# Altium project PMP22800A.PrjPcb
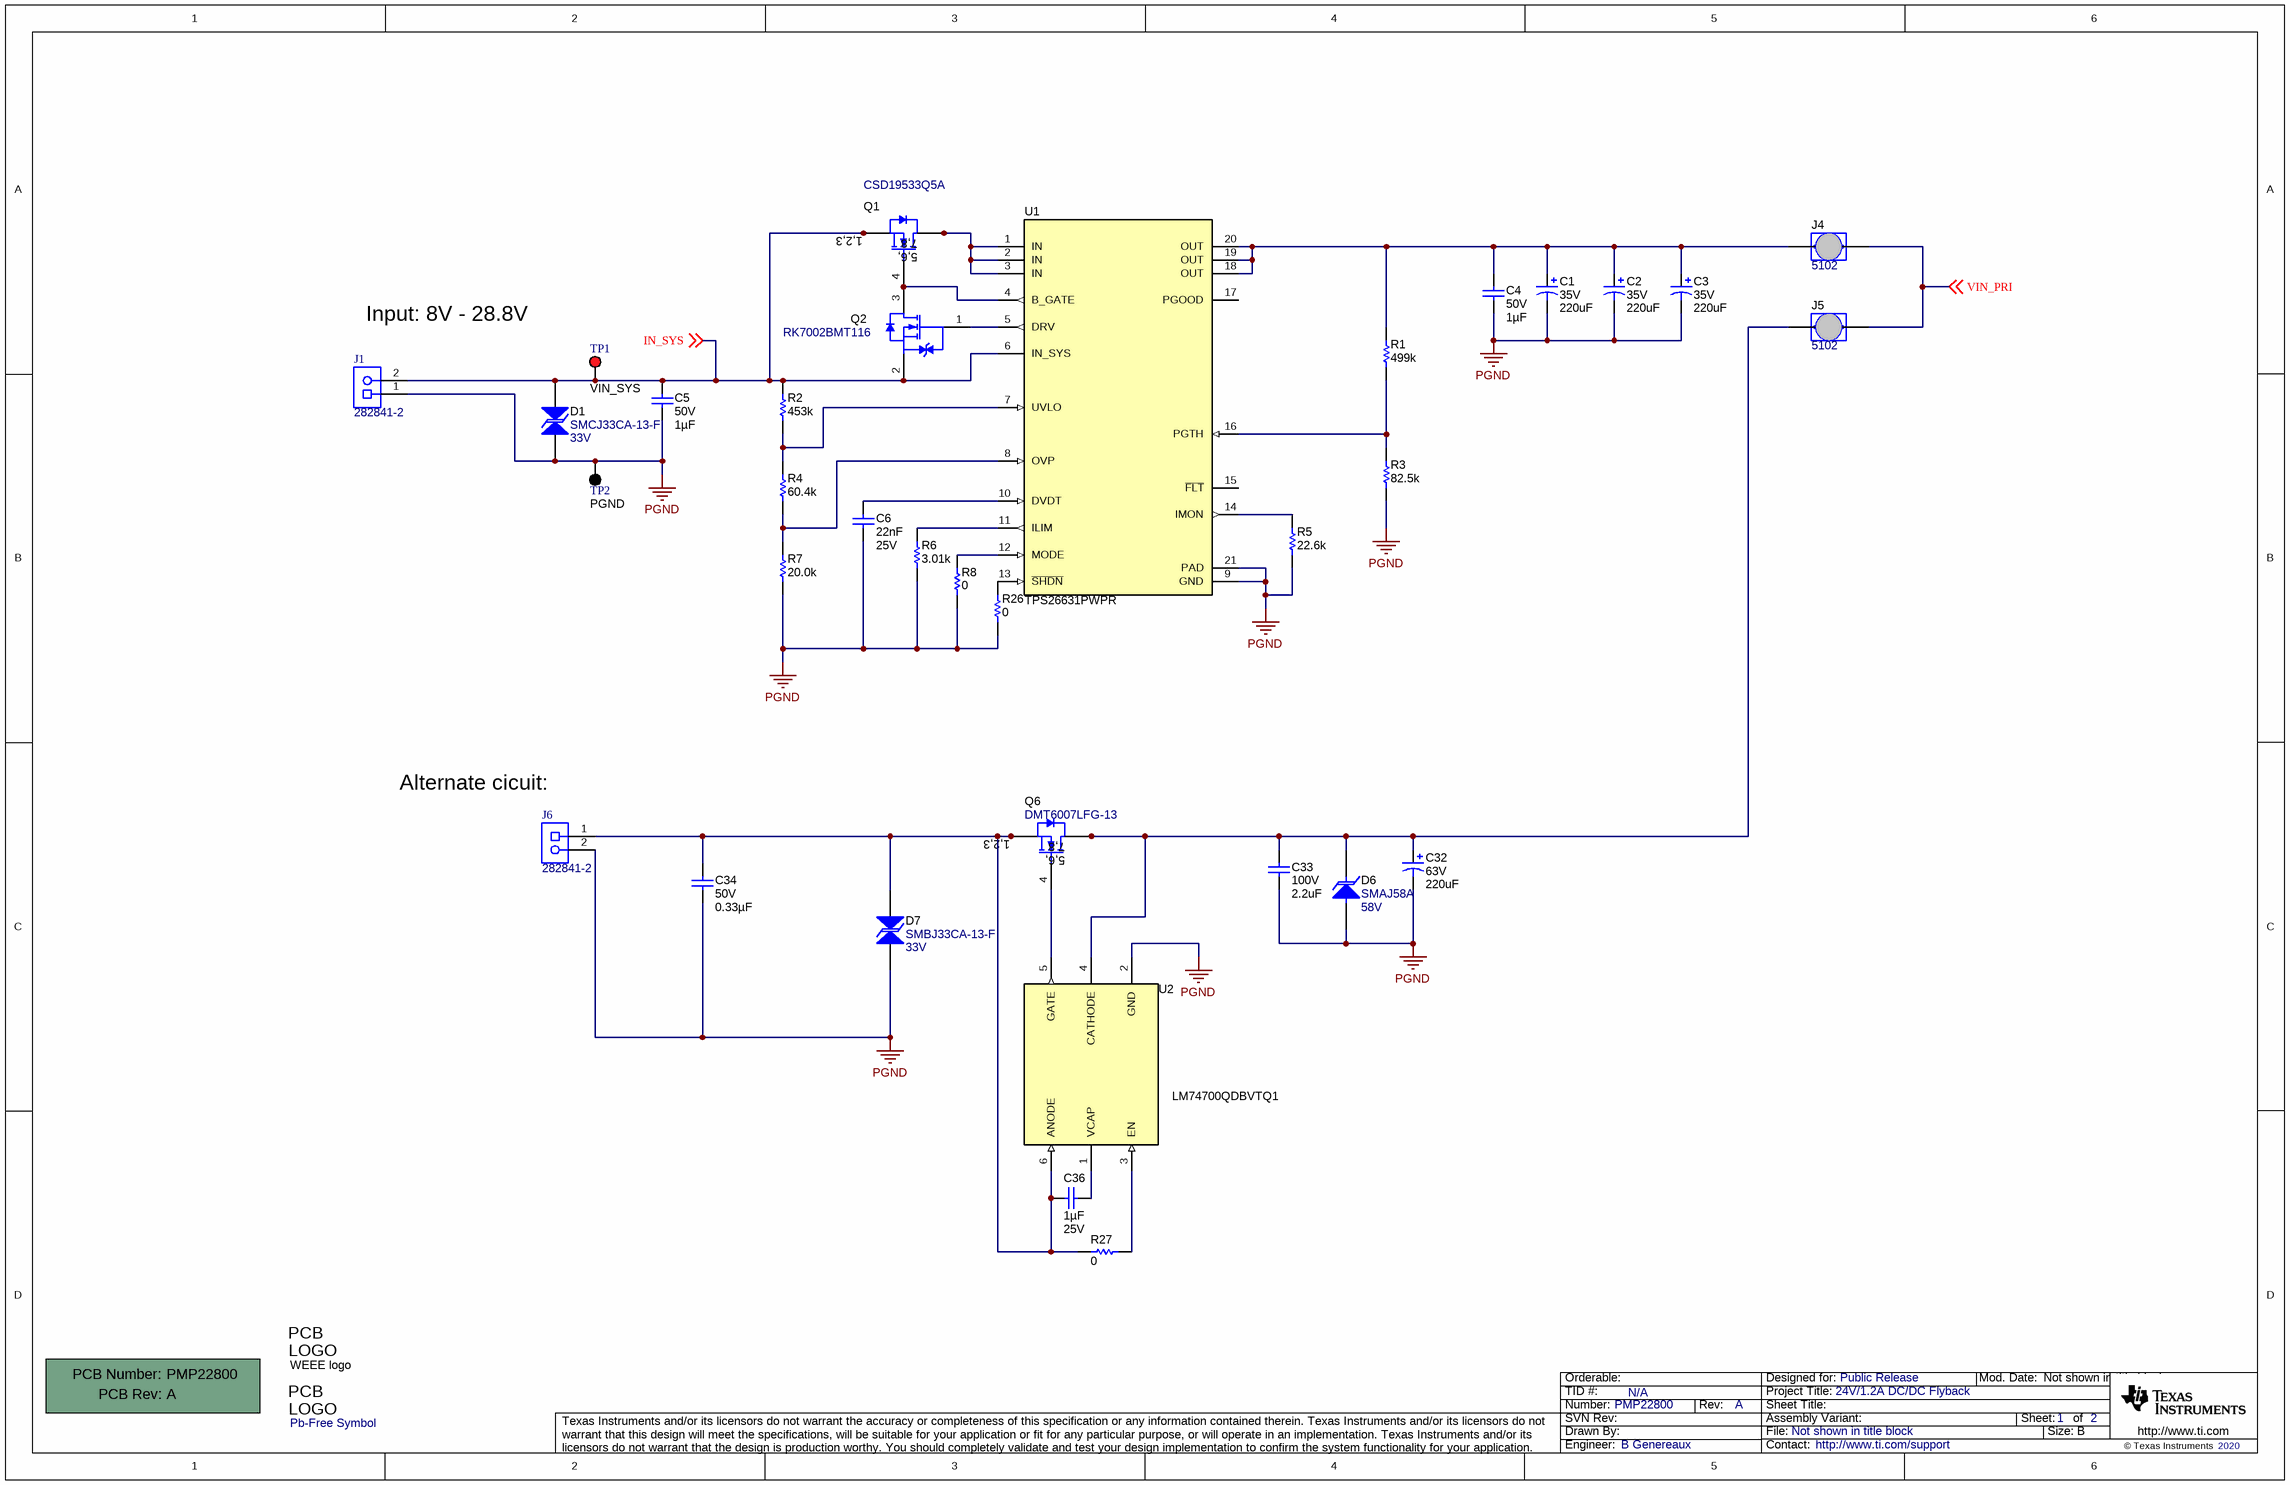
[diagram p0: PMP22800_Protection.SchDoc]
CopyrightYear: 2020; PCB_Rev: A; PRJ_Customer: Public Release; PRJ_Engineer: B Genereaux; PRJ_Number: PMP22800; PRJ_Title: 24V/1.2A DC/DC Flyback; SCH_Rev: A; TechSupport: http://www.ti.com/support; TID: N/A
2 sheets, 98 parts. Net scope: global (net labels, ports and power ports of the same name join across sheets).
Board file: PMP22800.PcbDoc
Sheets:
  PMP22800_Protection.SchDoc
  PMP22800_Power.SchDoc

## Sheet PMP22800_Protection.SchDoc
size 431 x 279 mm; Date: Not shown in title block; ApprovedBy: Not shown in title block; CheckedBy: Not shown in title block; Author: Not shown in title block; CompanyName: Not shown in title block; Engineer: Not shown in title block; Organization: Not shown in title block; Address1: Not shown in title block; Address2: Not shown in title block; Address3: Not shown in title block; Address4: Not shown in title block; DocumentNumber: 1; Revision: Use project parameter SCH_Rev; SheetNumber: 1; SheetTotal: 2; PageSetup: Record=PageOptions¦CenterHorizontal=True¦CenterVertical=True¦PrintScale=1.00¦XCorrection=1.00¦YCorrection=1.00¦PrintKind=0¦BorderSize=5000000¦LeftOffset=0¦BottomOffset=0¦Orientation=2¦PaperLength=1000¦PaperWidth=1000¦Scale=100¦PaperSource=15¦PrintQuality=600¦MediaType=1¦DitherType=10¦PaperKind=Letter¦PrintScaleMode=1

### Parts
!PCB1  Printed Circuit Board  (value not drawn)  (mechanical)
C1  VDC_V: 35V  ValueDisplayed: 220uF  [KZN_800x1500]  (hidden comment: EKZN350ELL221MH15D)
C2  VDC_V: 35V  ValueDisplayed: 220uF  [KZN_800x1500]  (hidden comment: EKZN350ELL221MH15D)
C3  VDC_V: 35V  ValueDisplayed: 220uF  [KZN_800x1500]  (hidden comment: EKZN350ELL221MH15D)
C4  VDC_V: 50V  Cap_F: 1µF  [0805_HV]  (hidden comment: GJ821BR71H105KA12L)
C5  VDC_V: 50V  Cap_F: 1µF  [0805_HV]  (hidden comment: GJ821BR71H105KA12L)
C6  Cap_F: 22nF  VDC_V: 25V  [0603]  (hidden comment: C0603C223K3RACTU)
C32  VDC_V: 63V  ValueDisplayed: 220uF  [SM_RADIAL_H13]  (hidden comment: EEV-FK1J221Q)
C33  VDC_V: 100V  ValueDisplayed: 2.2uF  [1210_210]  (hidden comment: C1210C225K1RACTU)
C34  VDC_V: 50V  ValueDisplayed: 0.33µF  [1206_180M]  (hidden comment: CGA5L2X8R1H334K160AA)
C36  Cap_F: 1µF  VDC_V: 25V  [0603]  (hidden comment: CGA3E1X7R1E105K080AD)
D1  SMCJ33CA-13-F  value 33V  [SMC_Bi]
D6  SMAJ58A  value 58V  [SMA]
D7  SMBJ33CA-13-F  value 33V  [SMB-Bi]
J1  282841-2  [TEC_282841-2]
J4  5102  [Keystone_5102]
J5  5102  [Keystone_5102]
J6  282841-2  [TEC_282841-2]
Logo1  WEEE logo  [WEEE_Minimum]  (no BOM)
Logo2  Pb-Free Symbol  [Pb-Free_Overlay_Medium]  (no BOM)
Q1  CSD19533Q5A  [DQJ0008A]
Q2  RK7002BMT116  [SOT-23_Rohm]
Q6  DMT6007LFG-13  [PowerDI3333-8]
R1  ValueDisplayed: 499k  [0603]  (hidden comment: RC0603FR-07499KL)
R2  ValueDisplayed: 453k  [0603]  (hidden comment: RC0603FR-07453KL)
R3  ValueDisplayed: 82.5k  [0603]  (hidden comment: RC0603FR-0782K5L)
R4  ValueDisplayed: 60.4k  [0603]  (hidden comment: RC0603FR-0760K4L)
R5  ValueDisplayed: 22.6k  [0603]  (hidden comment: RC0603FR-0722K6L)
R6  ValueDisplayed: 3.01k  [0603]  (hidden comment: RC0603FR-073K01L)
R7  ValueDisplayed: 20.0k  [0603]  (hidden comment: RC0603FR-0720KL)
R8  ValueDisplayed: 0  [0603]  (hidden comment: RMCF0603ZT0R00)
R26  ValueDisplayed: 0  [0603]  (hidden comment: RMCF0603ZT0R00)
R27  ValueDisplayed: 0  [0603]  (hidden comment: RMCF0603ZT0R00)
TP1  VIN_SYS  [Keystone5010]
TP2  PGND  [Keystone5011]
U1  TPS26631PWPR  [PWP0020T_N]
U2  LM74700QDBVTQ1  [DBV0006A_N]

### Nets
PGND: C1.2(-) C2.2(-) C3.2(-) C4.2 C5.2 C6.2 C32.2(-) C33.2 C34.2 D1.1 D6.2(A) D7.1 J1.1 J6.2 R3.1 R5.2 R6.2 R7.1 R8.1 R26.1 TP2.1 U1.9(GND) U1.21(PAD) U2.2(GND)
IN_SYS: C5.1 D1.2 J1.2 Q1.1(S) Q1.2(S) Q1.3(S) Q2.2(S) R2.2 TP1.1 U1.6(IN_SYS) ; off-sheet IN_SYS
VIN_PRI: J4.2 J5.2 ; off-sheet VIN_PRI
NetC1_1: C1.1(+) C2.1(+) C3.1(+) C4.1 J4.1 R1.2 U1.18(OUT) U1.19(OUT) U1.20(OUT)
NetC6_1: C6.1 U1.10(DVDT)
NetC32_1: C32.1(+) C33.1 D6.1(K) J5.1 Q6.5(D) Q6.6(D) Q6.7(D) Q6.8(D) Q6.9(D) U2.4(CATHODE)
NetC34_1: C34.1 C36.1 D7.2 J6.1 Q6.1(S) Q6.2(S) Q6.3(S) R27.2 U2.6(ANODE)
NetC36_2: C36.2 U2.1(VCAP)
NetQ1_4: Q1.4(G) Q2.3(D) U1.4(B_GATE)
NetQ1_5: Q1.5(D) Q1.6(D) Q1.7(D) Q1.8(D) Q1.9(D) U1.1(IN) U1.2(IN) U1.3(IN)
NetQ2_1: Q2.1(G) U1.5(DRV)
NetQ6_4: Q6.4(G) U2.5(GATE)
NetR1_1: R1.1 R3.2 U1.16(PGTH)
NetR2_1: R2.1 R4.2 U1.7(UVLO)
NetR4_1: R4.1 R7.2 U1.8(OVP)
NetR5_1: R5.1 U1.14(IMON)
NetR6_1: R6.1 U1.11(ILIM)
NetR8_2: R8.2 U1.12(MODE)
NetR26_2: R26.2 U1.13(~{SHDN})
NetR27_1: R27.1 U2.3(EN)

Not connected (* = marked no-connect by the designer): U1 15(~{FLT}) 17(PGOOD)

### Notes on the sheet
- Input: 8V - 28.8V
- (near J6) Alternate cicuit:

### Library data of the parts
!PCB1 = CMP-0003618-2: Manufacturer: Any; PartNumber: PMP22800
C1-C3 = CMP-0010431-2: CAP, AL, 220 uF, 35 V, +/- 20%, 0.059 ohm, TH; Manufacturer: Chemi-Con; TaMin_C: -40°C; ESR_ohm: 0.059; Polarized: Y; SizeAreaWB_mm2: 100; U/M: EA; Value: 220uF; TaMax_C: 105°C; SizeZ_mm: 16.5; SizeX_mm: 8; Cap_Case: 8x15mm; SizeArea_mm2: 64; CompType: Capacitor; Cap_F: 220µF; IRMS_A: 1.6A; AEC Category: Q200
C4 C5 = CMP-0750127-1: CAP, CERM, 1 µF, 50 V,+/- 10%, X7R, 0805; Manufacturer: MuRata; U/M: EA; SizeArea_mm2: 2.5; SizeAreaWB_mm2: 6.75; Cap_Case: 0805; Polarized: N; SizeZ_mm: 1.45; SizeX_mm: 2; TaMin_C: -55°C; Value: 1uF; TaMax_C: 125°C; SizeY_mm: 1.25; AEC Category: Q200
C6 = CMP-0006899-4: CAP, CERM, 0.022 uF, 25 V, +/- 10%, X7R, 0603; Manufacturer: Kemet; TaMin_C: -55°C; Polarized: N; SizeAreaWB_mm2: 4.68; Value1: Unknown; U/M: EA; TaMax_C: 125°C; SizeZ_mm: 1; SizeX_mm: 1.6; SizeY_mm: 0.8; SizeArea_mm2: 1.28; AEC Category: Q200
C32 = CMP-0011214-2: CAP, AL, 220 uF, 63 V, +/- 20%, 0.16 ohm, AEC-Q200 Grade 2, SMD; Manufacturer: Panasonic; TaMin_C: -55°C; ESR_ohm: 0.16; Polarized: Y; SizeAreaWB_mm2: 263.5; U/M: EA; Value: 220uF; TaMax_C: 105°C; SizeZ_mm: 13.5; SizeX_mm: 15; Cap_Case: H13; SizeArea_mm2: 202.5; CompType: Capacitor; Cap_F: 220µF; IRMS_A: 800mA; AEC Grade: 2; AEC Category: Q200
C33 = CMP-0009084-1: CAP, CERM, 2.2 uF, 100 V, +/- 10%, X7R, 1210; Manufacturer: Kemet; TaMin_C: -55°C; Polarized: N; SizeAreaWB_mm2: 14.7; Value1: Unknown; U/M: EA; Value: 2.2uF; TaMax_C: 125°C; SizeZ_mm: 2.1; SizeX_mm: 3.2; SizeY_mm: 2.5; Cap_Case: 1210; SizeArea_mm2: 8; Cap_F: 2.2µF; AEC Category: Q200
C34 = CMP-0078294-1: CAP, CERM, 0.33 µF, 50 V,+/- 10%, X8R, AEC-Q200 Grade 0, 1206; Manufacturer: TDK; TaMin_C: -55°C; Polarized: N; SizeAreaWB_mm2: 10.92; U/M: EA; Value: 0.33uF; TaMax_C: 150°C; SizeZ_mm: 1.8; SizeX_mm: 3.2; SizeY_mm: 1.6; Cap_Case: 1206; SizeArea_mm2: 5.12; AEC Qualified: Y; Cap_F: 330nF; AEC Grade: 0; AEC Category: Q200
C36 = CMP-0082523-1: CAP, CERM, 1 µF, 25 V,+/- 10%, X7R, AEC-Q200 Grade 1, 0603; Manufacturer: TDK; SizeAreaWB_mm2: 4.68; SizeArea_mm2: 1.28; AEC Qualified: Y; AEC Category: Q200; Value: 1uF; TaMax_C: 125°C; SizeZ_mm: 1; Polarized: N; TaMin_C: -55°C; SizeY_mm: 0.8; U/M: EA; SizeX_mm: 1.6
D1 = CMP-0086205-2: Diode, TVS, Bi, 33 V, 53.3 Vc, 1500 W, 200 A, SMC; Manufacturer: Diodes Inc.; Vc: 53.3V; AEC Category: Q101; AEC Qualified: N; Vbr_Max: 40.6V; SizeZ_mm: 2.62; SizeArea_mm2: 50.5686; Ppk: 1.5kW; SizeAreaWB_mm2: 83.2686; SizeX_mm: 8.13; SizeY_mm: 6.22; Vbr_Min: 36.7V; Ipp: 200A
D6 = CMP-0005485-3: Diode, TVS, Uni, 58 V, SMA; Manufacturer: Diodes Inc.; SizeX_mm: 5.59; AEC Category: Q101; SizeY_mm: 2.92; SizeArea_mm2: 16.3228; SizeZ_mm: 2.87; Ppk: 400W; SizeAreaWB_mm2: 37.3428
D7 = CMP-0005564-3: Diode, TVS, Bi, 33 V, SMB; Manufacturer: Diodes Inc.; SizeX_mm: 5.6; Ppk: 600W; SizeAreaWB_mm2: 44.156; SizeZ_mm: 2.6; SizeArea_mm2: 21.336; SizeY_mm: 3.81; AEC Category: Q101
J1 J6 = CMP-0054973-1: Terminal Block, 2x1, 5.08mm, TH; Manufacturer: TE Connectivity; CNHeader: FALSE; Green_Lifecycle: Active; Green_REACh: Passed; CT: TRUE
J4 J5 = CMP-0055135-1: Shorting Jumper, 5.375mm, 2 Position, Tin, SMT; Manufacturer: Keystone; CNHeader: FALSE; Pitch_mm: 5.375
Logo1 = CMP-0074769-1
Logo2 = CMP-0074839-1: SymbolCreator: a0412235
Q1 = CMP-0000960-2: MOSFET, N-CH, 100 V, 13 A, DQJ0008A (VSONP-8); Alternate Manufacturer: None; Manufacturer: Texas Instruments; SizeZ_mm: 1.1; ChType: N; Value2: 27 nC; VdsMax_V: 100V; SizeX_mm: 6; SizeY_mm: 4.9; Vgs_V: 20V; QgTyp_nC: 27; Value: 100V; SizeArea_mm2: 29.4; AEC Category: Q101; IdsMax_A: 13A; SizeAreaWB_mm2: 55.2; U/M: EA
Q2 = CMP-0000860-2: MOSFET, N-CH, 60 V, 0.25 A, SOT-23; Alternate Manufacturer: None; Manufacturer: Rohm; AEC Qualified: N; VdsMax_V: 60V; Vgs_V: 20V; IdsMax_A: 250mA; Rdson45_ohm: 3; SizeZ_mm: 0.95; SizeArea_mm2: 6.96; AEC Category: Q101; SizeAreaWB_mm2: 13.26; SizeY_mm: 2.9; Value: 60V; U/M: EA; SizeX_mm: 2.4; ChMode: Enhancement
Q6 = CMP-0067553-1: MOSFET, N-CH, 60 V, 15 A, AEC-Q101, 8-PowerVDFN; Alternate Manufacturer: None; Manufacturer: Diodes Inc.; Rdson45_ohm: 8.5m; QgTyp_nC: 41.3; SizeAreaWB_mm2: 18.49; Vgs_V: 20V; Value1: 0.0085 ohm; VdsMax_V: 60V; U/M: EA; Value: 60V; IdsMax_A: 15A; SizeZ_mm: 0.8; SizeX_mm: 3.3; Value2: 41.3 nC; SizeArea_mm2: 10.89; ChType: N; AEC Qualified: Y; AEC Category: Q101
R1 = CMP-0023140-4: RES, 499 k, 1%, 0.1 W, 0603; Manufacturer: Yageo; Power_W: 100mW; TempCo: 100 ppm/C; Value: 499k; EIA_Code: E96; SizeX_mm: 1.6; SizeY_mm: 0.8; SizeZ_mm: 1; Value2: 0.1W; SizeArea_mm2: 1.28; AEC Qualified: N; VDC_V: 75V; AEC Category: Q200; SizeAreaWB_mm2: 4.68
R2 = CMP-0023120-4: RES, 453 k, 1%, 0.1 W, 0603; Manufacturer: Yageo; Power_W: 100mW; TempCo: 100 ppm/C; Value: 453k; EIA_Code: E96; SizeX_mm: 1.6; SizeY_mm: 0.8; SizeZ_mm: 1; Value2: 0.1W; SizeArea_mm2: 1.28; AEC Qualified: N; VDC_V: 75V; AEC Category: Q200; SizeAreaWB_mm2: 4.68
R3 = CMP-0023291-5: RES, 82.5 k, 1%, 0.1 W, 0603; Manufacturer: Yageo; Power_W: 100mW; TempCo: 100 ppm/C; Value_Code: 82k5; Value: 82.5k; EIA_Code: E96; SizeX_mm: 1.6; SizeY_mm: 0.8; SizeZ_mm: 1; Value2: 0.1W; SizeArea_mm2: 1.28; AEC Qualified: N; VDC_V: 75V; AEC Category: Q200; SizeAreaWB_mm2: 4.68
R4 = CMP-0023212-5: RES, 60.4 k, 1%, 0.1 W, 0603; Manufacturer: Yageo; Power_W: 100mW; TempCo: 100 ppm/C; Value_Code: 60k4; Value: 60.4k; EIA_Code: E96; SizeX_mm: 1.6; SizeY_mm: 0.8; SizeZ_mm: 1; Value2: 0.1W; SizeArea_mm2: 1.28; AEC Qualified: N; VDC_V: 75V; AEC Category: Q200; SizeAreaWB_mm2: 4.68
R5 = CMP-0022924-5: RES, 22.6 k, 1%, 0.1 W, 0603; Manufacturer: Yageo; Power_W: 100mW; TempCo: 100 ppm/C; Value_Code: 22k6; Value: 22.6k; EIA_Code: E96; SizeX_mm: 1.6; SizeY_mm: 0.8; SizeZ_mm: 1; Value2: 0.1W; SizeArea_mm2: 1.28; AEC Qualified: N; VDC_V: 75V; AEC Category: Q200; SizeAreaWB_mm2: 4.68
R6 = CMP-0023076-5: RES, 3.01 k, 1%, 0.1 W, 0603; Manufacturer: Yageo; Power_W: 100mW; TempCo: 100 ppm/C; Value_Code: 3k01; Value: 3.01k; EIA_Code: E96; SizeX_mm: 1.6; SizeY_mm: 0.8; SizeZ_mm: 1; Value2: 0.1W; SizeArea_mm2: 1.28; AEC Qualified: N; VDC_V: 75V; AEC Category: Q200; SizeAreaWB_mm2: 4.68
R7 = CMP-0022906-5: RES, 20.0 k, 1%, 0.1 W, 0603; Manufacturer: Yageo; Power_W: 100mW; TempCo: 100 ppm/C; Value_Code: 20k0; Value: 20.0k; EIA_Code: E96; Res_ohm: 20k; SizeX_mm: 1.6; SizeY_mm: 0.8; SizeZ_mm: 1; Value2: 0.1W; SizeArea_mm2: 1.28; AEC Qualified: N; VDC_V: 75V; AEC Category: Q200; SizeAreaWB_mm2: 4.68
R8 R26 R27 = CMP-0023343-3: RES, 0, 1%, 0.1 W, AEC-Q200 Grade 0, 0603; Manufacturer: Stackpole Electronics Inc; Power_W: 100mW; TempCo: ppm/C; U/M: EA; Value: 0; SizeX_mm: 1.6; SizeY_mm: 0.8; SizeZ_mm: 1; Value2: 0.1W; SizeArea_mm2: 1.28; AEC Qualified: Y; AEC Category: Q200
TP1 = CMP-0055147-1: Test Point, Multipurpose, Red, TH; Manufacturer: Keystone; CNHeader: FALSE; Green_Lifecycle: Active; Green_REACh: Passed; ContactFinish: Silver; CT: TRUE
TP2 = CMP-0055148-1: Test Point, Multipurpose, Black, TH; Manufacturer: Keystone; CNHeader: FALSE; Green_Lifecycle: Active; Green_REACh: Passed; ContactFinish: Silver; CT: TRUE
U1 = CMP-0860095-3: 60-V, 6-A Power limiting, surge protection industrial eFuse, PWP0020T (HTSSOP-20); Manufacturer: Texas Instruments; SizeZ_mm: 1.2; SizeArea_mm2: 41.6; AEC Qualified: N; SizeY_mm: 6.5; AEC Category: Q200; CompType: IC; SizeX_mm: 6.4; SizeAreaWB_mm2: 71.4
U2 = CMP-0079180-1: Low Iq Always ON Smart Diode Controller, DBV0006A (SOT-23-6); Alternate PartNumber: LM74700QDBVRQ1; Alternate Manufacturer: Texas Instruments; SizeAreaWB_mm2: 14.82; SizeZ_mm: 1.45; SizeX_mm: 2.8; SizeY_mm: 2.9; SizeArea_mm2: 8.12; CompType: IC; AEC Qualified: Y; AEC Category: Q200

## Sheet PMP22800_Power.SchDoc
size 431 x 279 mm; Date: Not shown in title block; ApprovedBy: Not shown in title block; CheckedBy: Not shown in title block; Author: Not shown in title block; CompanyName: Not shown in title block; Engineer: Not shown in title block; Organization: Not shown in title block; Address1: Not shown in title block; Address2: Not shown in title block; Address3: Not shown in title block; Address4: Not shown in title block; DocumentNumber: 2; Revision: Use project parameter SCH_Rev; SheetNumber: 2; SheetTotal: 2; PageSetup: Record=PageOptions¦CenterHorizontal=True¦CenterVertical=True¦PrintScale=1.00¦XCorrection=1.00¦YCorrection=1.00¦PrintKind=0¦BorderSize=5000000¦LeftOffset=0¦BottomOffset=0¦Orientation=2¦PaperLength=1000¦PaperWidth=1000¦Scale=100¦PaperSource=15¦PrintQuality=600¦MediaType=1¦DitherType=10¦PaperKind=Letter¦PrintScaleMode=1
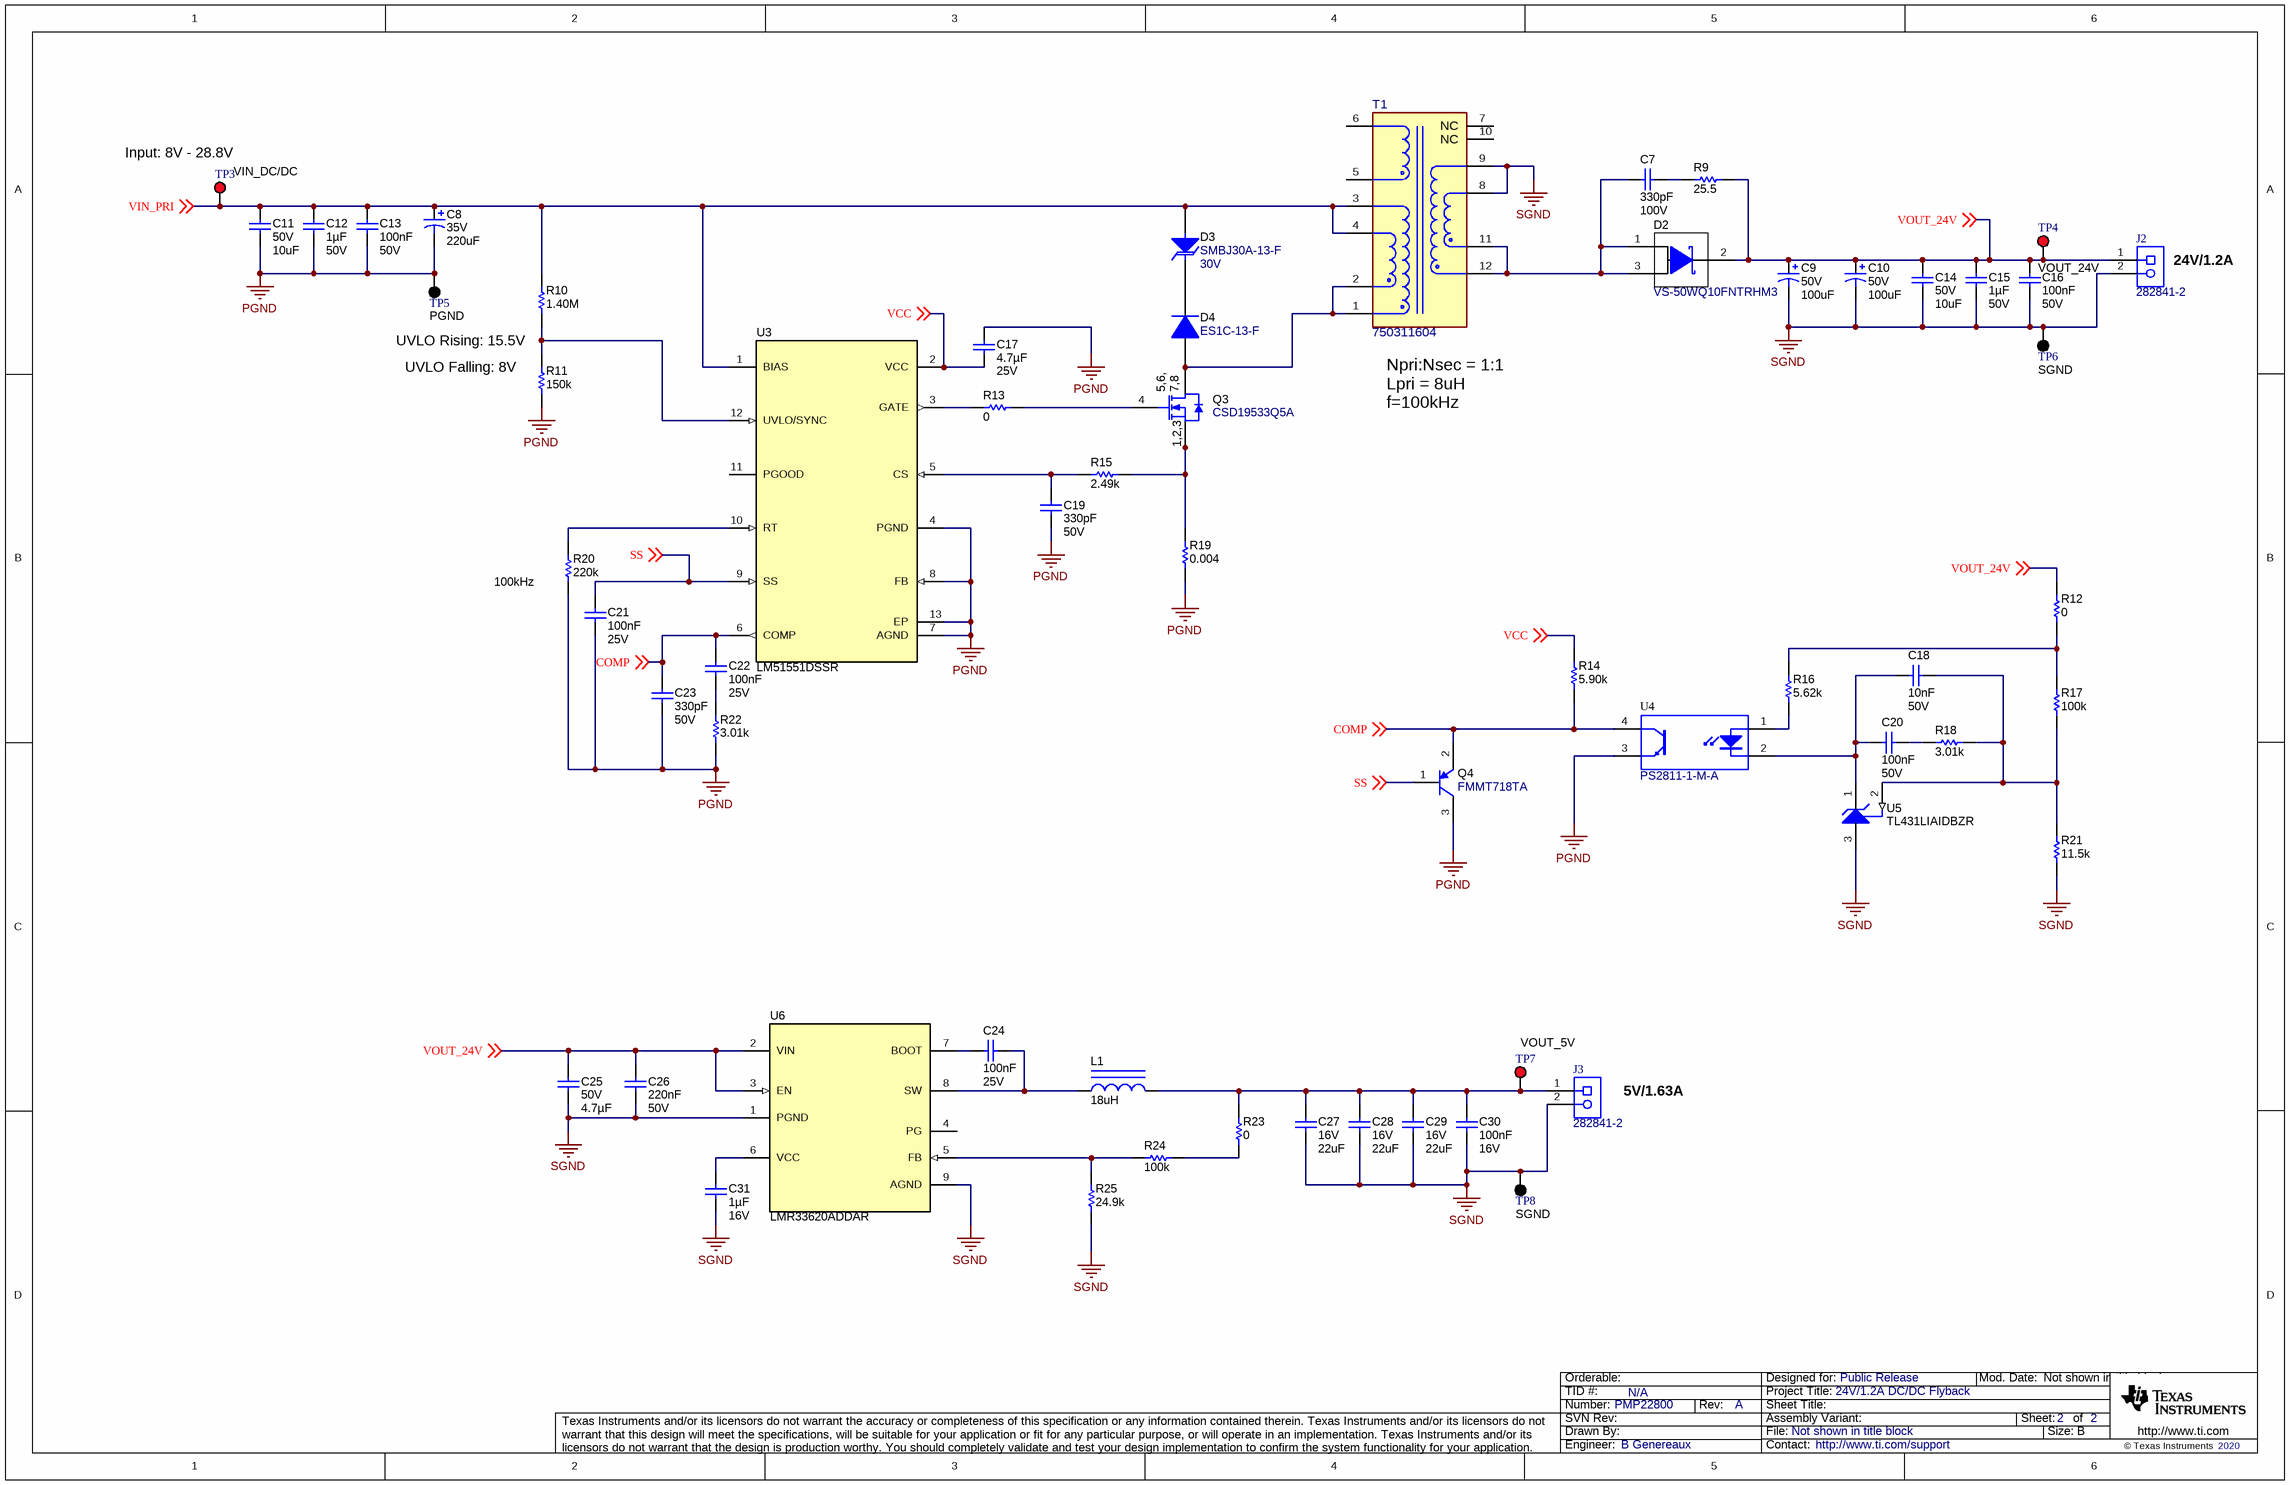
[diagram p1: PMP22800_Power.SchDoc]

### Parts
C7  Cap_F: 330pF  VDC_V: 100V  [0805_HV]  (hidden comment: 08051C331KAT2A)
C8  VDC_V: 35V  ValueDisplayed: 220uF  [KZN_800x1500]  (hidden comment: EKZN350ELL221MH15D)
C9  VDC_V: 50V  ValueDisplayed: 100uF  [HXB_JA0]  (hidden comment: HHXB500ARA101MJA0G)
C10  VDC_V: 50V  ValueDisplayed: 100uF  [HXB_JA0]  (hidden comment: HHXB500ARA101MJA0G)
C11  VDC_V: 50V  ValueDisplayed: 10uF  [1206_180M]  (hidden comment: CL31B106KBHNNNE)
C12  Cap_F: 1µF  VDC_V: 50V  [0805_HV]  (hidden comment: CL21B105KBFNFNE)
C13  Cap_F: 100nF  VDC_V: 50V  [0603]  (hidden comment: 06035C104JAT2A)
C14  VDC_V: 50V  ValueDisplayed: 10uF  [1206_180M]  (hidden comment: CL31B106KBHNNNE)
C15  Cap_F: 1µF  VDC_V: 50V  [0805_HV]  (hidden comment: CL21B105KBFNFNE)
C16  Cap_F: 100nF  VDC_V: 50V  [0603]  (hidden comment: 06035C104JAT2A)
C17  Cap_F: 4.7µF  VDC_V: 25V  [0805_HV]  (hidden comment: C2012X7R1E475K125AB)
C18  Cap_F: 10nF  VDC_V: 50V  [0603]  (hidden comment: C0603C103K5RACTU)
C19  Cap_F: 330pF  VDC_V: 50V  [0603]  (hidden comment: C0603C331K5RACTU)
C20  Cap_F: 100nF  VDC_V: 50V  [0603]  (hidden comment: 06035C104JAT2A)
C21  Cap_F: 100nF  VDC_V: 25V  [0603]  (hidden comment: C0603C104J3RAC)
C22  Cap_F: 100nF  VDC_V: 25V  [0603]  (hidden comment: C0603X104K3RACTU)
C23  Cap_F: 330pF  VDC_V: 50V  [0603]  (hidden comment: C0603C331K5RACTU)
C24  Cap_F: 100nF  VDC_V: 25V  [0603]  (hidden comment: C0603X104K3RACTU)
C25  VDC_V: 50V  ValueDisplayed: 4.7µF  [1206_190M]  (hidden comment: C3216X7R1H475K160AE)
C26  Cap_F: 220nF  VDC_V: 50V  [0603]  (hidden comment: C1608X7R1H224K080AB)
C27  VDC_V: 16V  ValueDisplayed: 22uF  [1210_280]  (hidden comment: C3225X7R1C226K250AC)
C28  VDC_V: 16V  ValueDisplayed: 22uF  [1210_280]  (hidden comment: C3225X7R1C226K250AC)
C29  VDC_V: 16V  ValueDisplayed: 22uF  [1210_280]  (hidden comment: C3225X7R1C226K250AC)
C30  Cap_F: 100nF  VDC_V: 16V  [0603]  (hidden comment: C0603C104J4RACTU)
C31  Cap_F: 1µF  VDC_V: 16V  [0603]  (hidden comment: CL10B105KO8NFNC)
D2  VS-50WQ10FNTRHM3  [DPAK]
D3  SMBJ30A-13-F  value 30V  [SMB]
D4  ES1C-13-F  [SMA]
J2  282841-2  [TEC_282841-2]
J3  282841-2  [TEC_282841-2]
L1  ValueDisplayed: 18uH  [WE-TPC_1038]  (hidden comment: 744066180)
Q3  CSD19533Q5A  [DQJ0008A]
Q4  FMMT718TA  [SOT-23]
R9  ValueDisplayed: 25.5  [0805_HV]  (hidden comment: CRCW080525R5FKEA)
R10  ValueDisplayed: 1.40M  [0603]  (hidden comment: CRCW06031M40FKEA)
R11  ValueDisplayed: 150k  [0603]  (hidden comment: RC0603FR-07150KL)
R12  ValueDisplayed: 0  [0603]  (hidden comment: RMCF0603ZT0R00)
R13  ValueDisplayed: 0  [0603]  (hidden comment: RMCF0603ZT0R00)
R14  ValueDisplayed: 5.90k  [0603]  (hidden comment: RC0603FR-075K9L)
R15  ValueDisplayed: 2.49k  [0603]  (hidden comment: RC0603FR-072K49L)
R16  ValueDisplayed: 5.62k  [0603]  (hidden comment: RC0603FR-075K62L)
R17  ValueDisplayed: 100k  [0603]  (hidden comment: RC0603FR-07100KL)
R18  ValueDisplayed: 3.01k  [0603]  (hidden comment: ERJ-P03F3011V)
R19  ValueDisplayed: 0.004  [2512]  (hidden comment: ERJ-M1WSF4M0U)
R20  ValueDisplayed: 220k  [0603]  (hidden comment: RC0603FR-07220KL)
R21  ValueDisplayed: 11.5k  [0603]  (hidden comment: RC0603FR-0711K5L)
R22  ValueDisplayed: 3.01k  [0603]  (hidden comment: ERJ-P03F3011V)
R23  ValueDisplayed: 0  [0603]  (hidden comment: RMCF0603ZT0R00)
R24  ValueDisplayed: 100k  [0603]  (hidden comment: RC0603FR-07100KL)
R25  ValueDisplayed: 24.9k  [0603]  (hidden comment: RC0603FR-0724K9L)
T1  750311604  [FP-750311604_SMT_XFRMR_29MM08_23MM11-MFG]
TP3  VIN_DC/DC  [Keystone5010]
TP4  VOUT_24V  [Keystone5010]
TP5  PGND  [Keystone5011]
TP6  SGND  [Keystone5011]
TP7  VOUT_5V  [Keystone5010]
TP8  SGND  [Keystone5011]
U3  LM51551DSSR  [DSS0012B]
U4  PS2811-1-M-A  [PS2811-1]
U5  TL431LIAIDBZR  [DBZ0003A_N]
U6  LMR33620ADDAR  [DDA0008J]

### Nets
PGND: C8.2(-) C11.2 C12.2 C13.2 C17.1 C19.1 C21.2 C23.2 Q4.3(C) R11.1 R19.1 R20.1 R22.1 TP5.1 U3.4(PGND) U3.7(AGND) U3.8(FB) U3.13(EP) U4.3(E)
SGND: C9.2(-) C10.2(-) C14.2 C15.2 C16.2 C25.2 C26.2 C27.2 C28.2 C29.2 C30.1 C31.2 J2.2 J3.2 R21.1 R25.1 T1.8 T1.9 TP6.1 TP8.1 U5.3(ANODE) U6.1(PGND) U6.9(AGND)
COMP: C22.1 C23.1 Q4.2(E) R14.1 U3.6(COMP) U4.4(C) ; off-sheet COMP
SS: C21.1 Q4.1(B) U3.9(SS) ; off-sheet SS
VCC: C17.2 R14.2 U3.2(VCC) ; off-sheet VCC
VIN_PRI: C8.1(+) C11.1 C12.1 C13.1 D3.2(A) R10.2 T1.3 T1.4 TP3.1 U3.1(BIAS) ; off-sheet VIN_PRI
VOUT_24V: C9.1(+) C10.1(+) C14.1 C15.1 C16.1 C25.1 C26.1 D2.2(K) J2.1 R9.2 R12.2 TP4.1 U6.2(VIN) U6.3(EN) ; off-sheet VOUT_24V
NetC7_1: C7.1 R9.1
NetC7_2: C7.2 D2.1(A) D2.3(A) T1.11 T1.12
NetC18_1: C18.1 R17.1 R18.1 R21.2 U5.2(REF)
NetC18_2: C18.2 C20.2 U4.2(K) U5.1(CATHODE)
NetC19_2: C19.2 R15.1 U3.5(CS)
NetC20_1: C20.1 R18.2
NetC22_2: C22.2 R22.2
NetC24_1: C24.1 U6.7(BOOT)
NetC24_2: C24.2 L1.1 U6.8(SW)
NetC27_1: C27.1 C28.1 C29.1 C30.2 J3.1 L1.2 R23.2 TP7.1
NetC31_1: C31.1 U6.6(VCC)
NetD3_1: D3.1(K) D4.1(K)
NetD4_2: D4.2(A) Q3.5(D) Q3.6(D) Q3.7(D) Q3.8(D) Q3.9(D) T1.1 T1.2
NetQ3_1: Q3.1(S) Q3.2(S) Q3.3(S) R15.2 R19.2
NetQ3_4: Q3.4(G) R13.2
NetR10_1: R10.1 R11.2 U3.12(UVLO/SYNC)
NetR12_1: R12.1 R16.2 R17.2
NetR13_1: R13.1 U3.3(GATE)
NetR16_1: R16.1 U4.1(A)
NetR20_2: R20.2 U3.10(RT)
NetR23_1: R23.1 R24.1
NetR24_2: R24.2 R25.2 U6.5(FB)

Not connected (* = marked no-connect by the designer): T1 5 6 7(NC) 10(NC); U3 11(PGOOD); U6 4(PG)

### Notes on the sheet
- (near TP3) Input: 8V - 28.8V
- (near J2) 24V/1.2A
- UVLO Rising: 15.5V
- (near R11) UVLO Falling: 8V
- (near T1) Npri:Nsec = 1:1
  Lpri = 8uH
  f=100kHz
- (near R20) 100kHz
- (near J3) 5V/1.63A

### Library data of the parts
C7 = CMP-0007553-2: CAP, CERM, 330 pF, 100 V, +/- 10%, X7R, 0805; Manufacturer: AVX; TaMin_C: -55°C; ESR_ohm: 0.563; Polarized: N; SizeAreaWB_mm2: 6.75; Value1: 0.563 ohm; U/M: EA; Value: 330pF; TaMax_C: 125°C; SizeZ_mm: 1.45; SizeX_mm: 2; SizeY_mm: 1.25; Cap_Case: 0805; SizeArea_mm2: 2.5; AEC Category: Q200
C8 = CMP-0010431-2: as C1 on sheet PMP22800_Protection
C9 C10 = CMP-0012269-3: CAP, Aluminum Polymer, 100 uF, 50 V, +/- 20%, 0.025 ohm, AEC-Q200 Grade 2, D10xL10mm SMD; Manufacturer: Chemi-Con; TaMin_C: -55°C; ESR_ohm: 0.025; Polarized: Y; Value: 100uF; TaMax_C: 105°C; Cap_Case: 10x10mm; CompType: Capacitor; Cap_F: 100µF; IRMS_A: 2A; AEC Grade: 2; AEC Category: Q200
C11 C14 = CMP-0008802-2: CAP, CERM, 10 uF, 50 V, +/- 10%, X7R, 1206; Manufacturer: Samsung; TaMin_C: -55°C; Polarized: N; SizeAreaWB_mm2: 10.92; Value1: Unknown; U/M: EA; Value: 10uF; TaMax_C: 125°C; SizeZ_mm: 1.8; SizeX_mm: 3.2; SizeY_mm: 1.6; Cap_Case: 1206; SizeArea_mm2: 5.12; Cap_F: 10µF; AEC Category: Q200
C12 C15 = CMP-0080611-1: CAP, CERM, 1 µF, 50 V,+/- 10%, X7R, 0805; Manufacturer: Samsung; TaMin_C: -55°C; Polarized: N; SizeAreaWB_mm2: 6.75; U/M: EA; Value: 1uF; TaMax_C: 125°C; SizeZ_mm: 1.45; SizeX_mm: 2; SizeY_mm: 1.25; Cap_Case: 0805; SizeArea_mm2: 2.5; AEC Category: Q200
C13 C16 C20 = CMP-0083854-1: CAP, CERM, 0.1 µF, 50 V,+/- 5%, X7R, 0603; Manufacturer: AVX; TaMin_C: -55°C; Polarized: N; Green_Lifecycle: Active; SizeAreaWB_mm2: 4.68; Green_REACh: Passed; U/M: EA; Value: 0.1uF; TaMax_C: 125°C; SizeZ_mm: 1; SizeX_mm: 1.6; SizeY_mm: 0.8; SizeArea_mm2: 1.28; AEC Category: Q200; ValueDisplayed: 0.1µF
C17 = CMP-0007870-2: CAP, CERM, 4.7 uF, 25 V, +/- 10%, X7R, 0805; Manufacturer: TDK; TaMin_C: -55°C; Polarized: N; SizeAreaWB_mm2: 6.75; Value1: Unknown; U/M: EA; Value: 4.7uF; TaMax_C: 125°C; SizeZ_mm: 1.45; SizeX_mm: 2; SizeY_mm: 1.25; Cap_Case: 0805; SizeArea_mm2: 2.5; AEC Category: Q200
C18 = CMP-0006854-4: CAP, CERM, 0.01 uF, 50 V, +/- 10%, X7R, 0603; Manufacturer: Kemet; TaMin_C: -55°C; Polarized: N; SizeAreaWB_mm2: 4.68; Value1: Unknown; U/M: EA; Value: 0.01uF; TaMax_C: 125°C; SizeZ_mm: 1; SizeX_mm: 1.6; SizeY_mm: 0.8; SizeArea_mm2: 1.28; AEC Category: Q200
C19 C23 = CMP-0006921-4: CAP, CERM, 330 pF, 50 V, +/- 10%, X7R, 0603; Manufacturer: Kemet; TaMin_C: -55°C; Polarized: N; SizeAreaWB_mm2: 4.68; Value1: Unknown; U/M: EA; Value: 330pF; TaMax_C: 125°C; SizeZ_mm: 1; SizeX_mm: 1.6; SizeY_mm: 0.8; SizeArea_mm2: 1.28; AEC Category: Q200
C21 = CMP-0006855-4: CAP, CERM, 0.1 uF, 25 V, +/- 5%, X7R, 0603; Manufacturer: Kemet; TaMin_C: -55°C; Polarized: N; SizeAreaWB_mm2: 4.68; Value1: Unknown; U/M: EA; Value: 0.1uF; TaMax_C: 125°C; SizeZ_mm: 1; SizeX_mm: 1.6; SizeY_mm: 0.8; SizeArea_mm2: 1.28; AEC Category: Q200
C22 C24 = CMP-0006979-5: CAP, CERM, 0.1 uF, 25 V, +/- 10%, X7R, 0603; Manufacturer: Kemet; TaMin_C: -55°C; Polarized: N; SizeAreaWB_mm2: 4.68; Value1: Unknown; U/M: EA; Value: 0.1uF; TaMax_C: 125°C; SizeZ_mm: 1; SizeX_mm: 1.6; SizeY_mm: 0.8; SizeArea_mm2: 1.28; AEC Category: Q200
C25 = CMP-0082522-1: CAP, CERM, 4.7 µF, 50 V,+/- 10%, X7R, 1206; Manufacturer: TDK; SizeAreaWB_mm2: 10.92; SizeArea_mm2: 5.12; AEC Qualified: N; AEC Category: Q200; Value: 4.7uF; TaMax_C: 125°C; SizeZ_mm: 1.9; TaMin_C: -55°C; SizeY_mm: 1.6; U/M: EA; SizeX_mm: 3.2; Cap_Case: 1206
C26 = CMP-0007047-4: CAP, CERM, 0.22 uF, 50 V, +/- 10%, X7R, 0603; Manufacturer: TDK; TaMin_C: -55°C; ESR_ohm: 0.021699; Polarized: N; SizeAreaWB_mm2: 4.68; Value1: 0.021699 ohm; U/M: EA; Value: 0.22uF; TaMax_C: 125°C; SizeZ_mm: 1; SizeX_mm: 1.6; SizeY_mm: 0.8; SizeArea_mm2: 1.28; IRMS_A: 1.12496A; AEC Category: Q200
C27-C29 = CMP-0009116-1: CAP, CERM, 22 uF, 16 V, +/- 10%, X7R, 1210; Manufacturer: TDK; TaMin_C: -55°C; ESR_ohm: 2.582m; Polarized: N; SizeAreaWB_mm2: 14.7; Value1: 0.002582 ohm; U/M: EA; Value: 22uF; TaMax_C: 125°C; SizeZ_mm: 2.8; SizeX_mm: 3.2; SizeY_mm: 2.5; SizeArea_mm2: 8; Cap_F: 22µF; IRMS_A: 4.57562A; AEC Category: Q200
C30 = CMP-0006857-4: CAP, CERM, 0.1 uF, 16 V, +/- 5%, X7R, 0603; Manufacturer: Kemet; TaMin_C: -55°C; Polarized: N; SizeAreaWB_mm2: 4.68; Value1: Unknown; U/M: EA; Value: 0.1uF; TaMax_C: 125°C; SizeZ_mm: 1; SizeX_mm: 1.6; SizeY_mm: 0.8; SizeArea_mm2: 1.28; AEC Category: Q200
C31 = CMP-0085537-1: CAP, CERM, 1 µF, 16 V,+/- 10%, X7R, 0603; Manufacturer: Samsung Electro-Mechanics; SizeZ_mm: 1; SizeY_mm: 0.8; TaMin_C: -55°C; AEC Qualified: N; U/M: EA; AEC Category: Q200; SizeAreaWB_mm2: 4.68; TaMax_C: 125°C; SizeX_mm: 1.6; Value: 1uF; SizeArea_mm2: 1.28
D2 = CMP-0028919-3: Diode, Schottky, 100 V, 5.5 A, AEC-Q101, DPAK; Manufacturer: Vishay-Semiconductor; SizeAreaWB_mm2: 101.7114; Green_Lifecycle: Not Set; SizeX_mm: 9.91; Io_A: 5.5A; Value2: 0.77V; SizeZ_mm: 2.29; AEC Category: Q101; Vf_V: 770mV; AEC Qualified: Y; Green_REACh: Incomplete; SizeArea_mm2: 64.8114; SizeY_mm: 6.54; Vr_V: 100V; Value: 100V; TJmax_C: 150°C
D3 = CMP-0005561-4: Diode, TVS, Uni, 30 V, 48.4 Vc, SMB; Manufacturer: Diodes Inc.; Vbr_Max: 38.3V; Vc: 48.4V; SizeAreaWB_mm2: 44.156; SizeX_mm: 5.6; Value1: 600W; Ipp: 12.4A; SizeArea_mm2: 21.336; SizeY_mm: 3.81; Vbr_Min: 33.3V; SizeZ_mm: 2.6; AEC Category: Q101
D4 = CMP-0029023-2: Diode, Superfast Rectifier, 150 V, 1 A, SMA; Manufacturer: Diodes Inc.; TJmax_C: 150°C; Vr_V: 150V; Value2: 0.92V; SizeX_mm: 5.59; Green_REACh: Incomplete; SizeAreaWB_mm2: 37.3428; Value: 150V; Vf_V: 920mV; Green_Lifecycle: Not Set; Value1: 1A; SizeZ_mm: 2.87; SizeArea_mm2: 16.3228; SizeY_mm: 2.92; AEC Category: Q101; RJC_CperW: 25
J2 J3 = CMP-0054973-1: as J1 on sheet PMP22800_Protection
L1 = CMP-0064445-2: Inductor, Shielded, 18 uH, 2.8 A, 0.054 ohm, SMD; Manufacturer: Wurth Elektronik; Isat: 3A @ 35% inductance drop; Irms: 2.8A @ 30C rise; Green_Lifecycle: Active; SizeAreaWB_mm2: 144; DCR_ohm: 0.054; Green_REACh: Passed; Value: 18uH; Imax_A: 2.8A; SizeZ_mm: 4.1; SizeX_mm: 10; SizeArea_mm2: 100; Ind_H: 18µH; AEC Category: Q200
Q3 = CMP-0000960-2: as Q1 on sheet PMP22800_Protection
Q4 = CMP-0000330-2: Transistor, PNP, 20 V, 1.5 A, SOT-23; Manufacturer: Diodes Inc.; TaMax_C: 150°C; Value2: 6; Value1: 1.5 A; Vcesat1_V: 20V; SizeX_mm: 2.5; SizeY_mm: 3; TaMin_C: -55°C; IcRated_A: 1.5A; CompType: BJT; SizeZ_mm: 1.1; Value: 20 V; SizeArea_mm2: 7.5; NPN: 0; PNP: 1; AEC Category: Q101; SizeAreaWB_mm2: 14; U/M: EA
R9 = CMP-0021081-3: RES, 25.5, 1%, 0.125 W, AEC-Q200 Grade 0, 0805; Manufacturer: Vishay-Dale; Power_W: 125mW; TempCo: 100 ppm/C; Value_Code: 25R5; Value: 25.5; EIA_Code: E96; SizeX_mm: 2; SizeY_mm: 1.25; SizeZ_mm: 1.45; Value2: 0.125W; SizeArea_mm2: 2.5; AEC Qualified: Y; VDC_V: 150V; AEC Category: Q200; AEC Grade: 0
R10 = CMP-0022153-4: RES, 1.40 M, 1%, 0.1 W, AEC-Q200 Grade 0, 0603; Manufacturer: Vishay-Dale; Power_W: 100mW; TempCo: 100 ppm/C; Value_Code: 1M40; Value: 1.40Meg; EIA_Code: E96; Res_ohm: 1.4M; SizeX_mm: 1.6; SizeY_mm: 0.8; SizeZ_mm: 1; Value2: 0.1W; SizeArea_mm2: 1.28; AEC Qualified: Y; VDC_V: 75V; AEC Category: Q200; AEC Grade: 0
R11 = CMP-0022808-4: RES, 150 k, 1%, 0.1 W, 0603; Manufacturer: Yageo; Power_W: 100mW; TempCo: 100 ppm/C; Value: 150k; EIA_Code: E96; SizeX_mm: 1.6; SizeY_mm: 0.8; SizeZ_mm: 1; Value2: 0.1W; SizeArea_mm2: 1.28; AEC Qualified: N; VDC_V: 75V; AEC Category: Q200; SizeAreaWB_mm2: 4.68
R12 R13 R23 = CMP-0023343-3: as R8 on sheet PMP22800_Protection
R14 = CMP-0023205-5: RES, 5.90 k, 1%, 0.1 W, 0603; Manufacturer: Yageo; Power_W: 100mW; TempCo: 100 ppm/C; Value_Code: 5k90; Value: 5.90k; EIA_Code: E96; Res_ohm: 5.9k; SizeX_mm: 1.6; SizeY_mm: 0.8; SizeZ_mm: 1; Value2: 0.1W; SizeArea_mm2: 1.28; AEC Qualified: N; VDC_V: 75V; AEC Category: Q200; SizeAreaWB_mm2: 4.68
R15 = CMP-0022990-5: RES, 2.49 k, 1%, 0.1 W, 0603; Manufacturer: Yageo; Power_W: 100mW; TempCo: 100 ppm/C; Value_Code: 2k49; Value: 2.49k; EIA_Code: E96; SizeX_mm: 1.6; SizeY_mm: 0.8; SizeZ_mm: 1; Value2: 0.1W; SizeArea_mm2: 1.28; AEC Qualified: N; VDC_V: 75V; AEC Category: Q200; SizeAreaWB_mm2: 4.68
R16 = CMP-0023202-5: RES, 5.62 k, 1%, 0.1 W, 0603; Manufacturer: Yageo; Power_W: 100mW; TempCo: 100 ppm/C; Value_Code: 5k62; Value: 5.62k; EIA_Code: E96; SizeX_mm: 1.6; SizeY_mm: 0.8; SizeZ_mm: 1; Value2: 0.1W; SizeArea_mm2: 1.28; AEC Qualified: N; VDC_V: 75V; AEC Category: Q200; SizeAreaWB_mm2: 4.68
R17 R24 = CMP-0022735-5: RES, 100 k, 1%, 0.1 W, 0603; Manufacturer: Yageo; Power_W: 100mW; TempCo: 100 ppm/C; Value: 100k; EIA_Code: E96; SizeX_mm: 1.6; SizeY_mm: 0.8; SizeZ_mm: 1; Value2: 0.1W; SizeArea_mm2: 1.28; AEC Qualified: N; VDC_V: 75V; AEC Category: Q200; SizeAreaWB_mm2: 4.68
R18 R22 = CMP-0022729-3: RES, 3.01 k, 1%, 0.2 W, 0603; Manufacturer: Panasonic; Power_W: 200mW; TempCo: 200 ppm/C; Value_Code: 3k01; U/M: EA; Value: 3.01k; EIA_Code: E96; SizeX_mm: 1.6; SizeY_mm: 0.8; SizeZ_mm: 1; Value2: 0.2W; SizeArea_mm2: 1.28; VDC_V: 150V; AEC Category: Q200
R19 = CMP-0015813-2: RES, 0.004, 1%, 1 W, 2512; Manufacturer: Panasonic; Power_W: 1W; TempCo: 350 ppm/C; Value_Code: 4L000; U/M: EA; Value: 0.004; Res_ohm: 4m; SizeX_mm: 6.3; SizeY_mm: 3.2; SizeZ_mm: 0.71; SizeArea_mm2: 20.16; AEC Category: Q200
R20 = CMP-0022917-4: RES, 220 k, 1%, 0.1 W, 0603; Manufacturer: Yageo; Power_W: 100mW; TempCo: 100 ppm/C; Value: 220k; SizeX_mm: 1.6; SizeY_mm: 0.8; SizeZ_mm: 1; Value2: 0.1W; SizeArea_mm2: 1.28; AEC Qualified: N; VDC_V: 75V; AEC Category: Q200; SizeAreaWB_mm2: 4.68
R21 = CMP-0022761-5: RES, 11.5 k, 1%, 0.1 W, 0603; Manufacturer: Yageo; Power_W: 100mW; TempCo: 100 ppm/C; Value_Code: 11k5; Value: 11.5k; EIA_Code: E96; SizeX_mm: 1.6; SizeY_mm: 0.8; SizeZ_mm: 1; Value2: 0.1W; SizeArea_mm2: 1.28; AEC Qualified: N; VDC_V: 75V; AEC Category: Q200; SizeAreaWB_mm2: 4.68
R25 = CMP-0022944-5: RES, 24.9 k, 1%, 0.1 W, 0603; Manufacturer: Yageo; Power_W: 100mW; TempCo: 100 ppm/C; Value_Code: 24k9; Value: 24.9k; EIA_Code: E96; SizeX_mm: 1.6; SizeY_mm: 0.8; SizeZ_mm: 1; Value2: 0.1W; SizeArea_mm2: 1.28; AEC Qualified: N; VDC_V: 75V; AEC Category: Q200; SizeAreaWB_mm2: 4.68
T1 = CMP-0091456-1: Power Transformers WE-FB Flyback 8.0uH 1.3 24V; Manufacturer: Wurth Electronics; Ind_H: 7.2µH; AEC Qualified: No; SizeZ_mm: 11.43mm; Rsec1_ohm: 0.035; DCR_ohm: 0.03; Ns1toNp: 1:1/1:1/2.4:1/1:1; Voltage_Isolation_Vrms: 1.5kV
TP3 TP4 TP7 = CMP-0055147-1: as TP1 on sheet PMP22800_Protection
TP5 TP6 TP8 = CMP-0055148-1: as TP2 on sheet PMP22800_Protection
U3 = CMP-0085932-2: 2.2-MHz Wide Input Nonsynchronous Boost, Sepic, Flyback Controller, DSS0012B (WSON-12); Manufacturer: Texas Instruments; Alternate PartNumber: LM51551DSST; SizeAreaWB_mm2: 12; SizeArea_mm2: 6; AEC Category: Q200; CompType: IC; AEC Qualified: N; SizeX_mm: 2; SizeZ_mm: 0.8; SizeY_mm: 3
U4 = CMP-0006156-4: Optocoupler, 2.5 kV, 100-200% CTR, SMT; Manufacturer: California Eastern Laboratories; CTR (Max): 200%; CTR (Min): 100%; Voltage_Isolation_Vrms: 2.5kV; Green_Lifecycle: Active; Green_REACh: Passed
U5 = CMP-0084729-1: Programmable Shunt Regulator with Optimized Reference Current, DBZ0003A (SOT-23-3); Manufacturer: Texas Instruments; SizeY_mm: 3; SizeZ_mm: 1.12; SizeX_mm: 2.5; SizeAreaWB_mm2: 14; CompType: IC; AEC Qualified: N; AEC Category: Q200; SizeArea_mm2: 7.5
U6 = CMP-0074756-2: 3.8V to 36V 3A/2A Synchronous Step-Down Voltage Regulator, DDA0008J (SOIC-8); Manufacturer: Texas Instruments; SizeX_mm: 5.99; SizeY_mm: 4.89; CompType: IC; SizeZ_mm: 1.7; SizeArea_mm2: 29.2911; SizeAreaWB_mm2: 55.0511; U/M: EA

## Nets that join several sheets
PGND: PMP22800_Protection (24 pins), PMP22800_Power (19 pins)
VIN_PRI: PMP22800_Protection (J4.2 J5.2), PMP22800_Power (10 pins)

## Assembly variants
001: not fitted C18 C23 D6 J5 R26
